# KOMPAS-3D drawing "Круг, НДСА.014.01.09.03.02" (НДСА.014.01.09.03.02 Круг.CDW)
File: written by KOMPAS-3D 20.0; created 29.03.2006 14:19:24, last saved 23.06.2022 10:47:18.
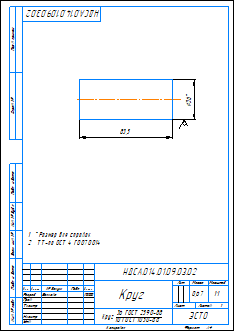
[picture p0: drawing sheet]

Sheet 1: A4, portrait

Document properties: Полное имя файла: НДСА.014.01.09.03.02 Круг.m3d; 282139817692: <item xmlns="http://appius.ru/pdm" xmlns:xs="http://www.w3.org/2001/XMLSchema" xmlns:xsi="http://www.w3.org/2001/XMLSchema-instance" xsi:type="item">  <element xmlns:d2p1="http://v8.1c.ru/8.1/data/enterprise/current-config" xsi:type="d2p1:CatalogRef.aps_Элемен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; PLM_CDWXDTO: <item xmlns="http://appius.ru/pdm" xmlns:xs="http://www.w3.org/2001/XMLSchema" xmlns:xsi="http://www.w3.org/2001/XMLSchema-instance" xsi:type="item">  <element xmlns:d2p1="http://v8.1c.ru/8.1/data/enterprise/current-config" xsi:type="d2p1:CatalogRef.aps_Элемен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; Масса: 0.667702

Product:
- Part/product: Круг  | designation НДСА.014.01.09.03.02
    Материал: Круг$d36 ГОСТ 2590-88;10 ГОСТ 1050-88$ (density 7856 kg/m3)
    Масса: 0.667702

Title block, sheet 1: Наименование: Круг; designation: НДСА.014.01.09.03.02; Материал: Круг 36 ГОСТ 2590-88 10 ГОСТ 1050-88; Масса: 0,67; scale: 1:1; Количество листов документа: 1; organisation: ЭСТО; Форматы листов документа: A4; stored path: D:\Work-Kompas 6\УКРД.762.00.00.00.00 Верх.стойка гидр.подъём\УКРД.762.02.00.00.00 Опора\УКРД.762.02.00.00.01 Круг.cdw; Разработал: Волкова; Разработал, date: 17.01.2020
Table, sheet 1:
  0;Material:VDE12371B5FDD453AAD3A0896F0FE5778;Sortament:V6A25FA24F2024846A417965BB2EC510D^SortamentEx:V3D6F3D024613455AB8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

Views: Спереди 1, Спереди
Referenced files in E:\НДСА.014.01.09.00.00 Верхняя стойка гидроподъемника\: НДСА.014.01.09.03.02 Круг.m3d
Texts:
  НДСА.014.01.09.03.02 Круг
Dimensions and other numbers on the sheet: 36; 83,5; 1:1; 1; 0,67; 17.01.2020

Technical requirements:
  1.  *Размер для справок.
  2.  Т.Т.-по ОСТ 4 ГО.070.014.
